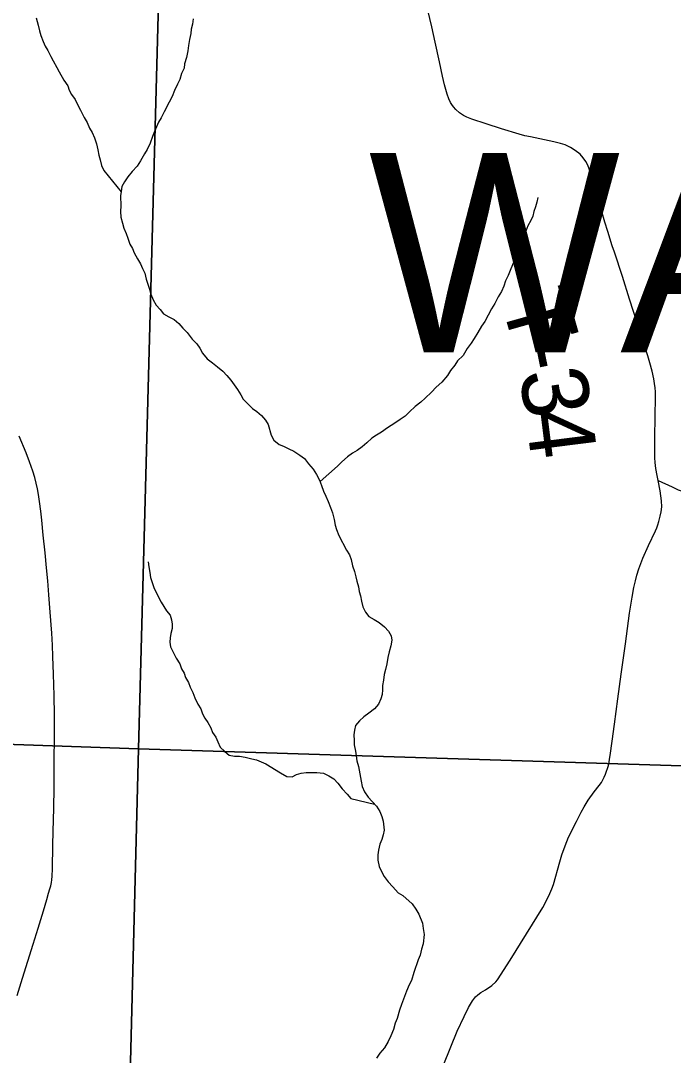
# Model space of a CAD drawing. Extents: x -7.9 to 76.1, y 0 to 22.
# Drawn here: x 6.095 to 6.653, y 14.979 to 15.864 of the extents above; entities that cross this region are included whole.
import ezdxf

# ---------------------------------------------------------------- set-up
doc = ezdxf.new("R2010")
doc.units = 0
for name, color, linetype in [('GM_X_Minor_River', 7, 'Continuous'), ('GM_X_Section', 7, 'Continuous'), ('GM_X_Township_Road', 7, 'Continuous'), ('GM_X_Township_Road_Text', 7, 'Continuous'), ('GM_X_Township_Text', 7, 'Continuous')]:
    doc.layers.add(name, color=color, linetype=linetype)

msp = doc.modelspace()

# ---------------------------------------------------------------- linework, layer by layer
at = {"layer": 'GM_X_Minor_River'}
for points in [[(6.10838, 15.86644), (6.10998, 15.86039), (6.11119, 15.85547), (6.11238, 15.85131), (6.11434, 15.84641), (6.11591, 15.84226), (6.11824, 15.83849), (6.12096, 15.8336), (6.12291, 15.82983), (6.12602, 15.82418), (6.12796, 15.82041), (6.13185, 15.81325), (6.13533, 15.80836), (6.13652, 15.80458), (6.13847, 15.80082), (6.14155, 15.79668), (6.1439, 15.79178), (6.14623, 15.78764), (6.14935, 15.78123), (6.15206, 15.77709), (6.15402, 15.77219), (6.15635, 15.76842), (6.1583, 15.7639), (6.15989, 15.7586), (6.1611, 15.75369), (6.16191, 15.74914), (6.16311, 15.74499), (6.16431, 15.74007), (6.16626, 15.73592), (6.1809, 15.71772)], [(6.24262, 15.86563), (6.24193, 15.86106), (6.24084, 15.85688), (6.24052, 15.85308), (6.23945, 15.84813), (6.23876, 15.8428), (6.23806, 15.83824), (6.237, 15.83253), (6.23518, 15.82719), (6.23485, 15.82339), (6.23264, 15.81881), (6.23119, 15.81385), (6.22935, 15.80966), (6.22677, 15.80431), (6.22456, 15.79934), (6.22197, 15.79437), (6.21791, 15.78597), (6.21533, 15.781), (6.2131, 15.77717), (6.21126, 15.77335), (6.20942, 15.76915), (6.20796, 15.76496), (6.20576, 15.75923), (6.20318, 15.75389), (6.20096, 15.75006), (6.19762, 15.74432), (6.19465, 15.73973), (6.19054, 15.73512), (6.18681, 15.73051), (6.18384, 15.7263), (6.18162, 15.72209), (6.18092, 15.71791), (6.18059, 15.71411), (6.1807, 15.70576), (6.18039, 15.70082), (6.18084, 15.69589), (6.18204, 15.69098), (6.18324, 15.68644), (6.1852, 15.68191), (6.18676, 15.67814), (6.18835, 15.67285), (6.19068, 15.66908), (6.19224, 15.66531), (6.19496, 15.66041), (6.19768, 15.6559), (6.19925, 15.65212), (6.2012, 15.64798), (6.2024, 15.64306), (6.20517, 15.63437), (6.20637, 15.63021), (6.20833, 15.6253), (6.21105, 15.62079), (6.21451, 15.61704), (6.21721, 15.61328)], [(6.53741, 15.71294), (6.53671, 15.70875), (6.53562, 15.70494), (6.53416, 15.70075), (6.53308, 15.69694), (6.53161, 15.69312), (6.52902, 15.68853), (6.52719, 15.68395), (6.52499, 15.67823), (6.52278, 15.67289), (6.52021, 15.66678), (6.518, 15.66219), (6.51655, 15.65724), (6.51435, 15.6519), (6.51215, 15.64617), (6.50994, 15.64159), (6.50848, 15.63701), (6.50627, 15.63243), (6.50368, 15.62784), (6.50072, 15.62211), (6.49775, 15.61751), (6.4922, 15.60681), (6.48923, 15.60259), (6.48627, 15.59724), (6.48292, 15.59226), (6.48033, 15.58805), (6.47698, 15.58345), (6.47364, 15.57771), (6.46877, 15.57309), (6.46655, 15.56927), (6.46282, 15.56466), (6.46022, 15.56045), (6.45537, 15.55469), (6.4505, 15.55045), (6.44638, 15.54622), (6.44114, 15.54122), (6.4374, 15.53775), (6.43252, 15.53389), (6.42765, 15.52927), (6.42391, 15.5258), (6.41978, 15.52271), (6.41527, 15.51961), (6.40888, 15.51573), (6.40362, 15.51186), (6.39948, 15.50953), (6.39535, 15.50681), (6.39123, 15.50296), (6.3871, 15.49949), (6.38298, 15.4964), (6.37884, 15.49406), (6.37471, 15.49097), (6.36984, 15.48673), (6.36609, 15.48288), (6.35114, 15.46966)], [(6.21721, 15.61328), (6.2218, 15.61069), (6.22638, 15.60847), (6.23022, 15.60511), (6.23369, 15.60098), (6.23753, 15.59724), (6.24177, 15.59161), (6.24562, 15.58749), (6.24833, 15.58373), (6.25066, 15.57958), (6.25452, 15.57471), (6.25911, 15.57135), (6.26333, 15.568), (6.26793, 15.56426), (6.27139, 15.56052), (6.27486, 15.55639), (6.27756, 15.55263), (6.28065, 15.5485), (6.28337, 15.54398), (6.28532, 15.54021), (6.29338, 15.53236), (6.29721, 15.52975), (6.30105, 15.52639), (6.30452, 15.52226), (6.30684, 15.5185), (6.30924, 15.50942), (6.31157, 15.50528), (6.31617, 15.50155), (6.31998, 15.50009), (6.32456, 15.49787), (6.32876, 15.49565), (6.33374, 15.4923), (6.33795, 15.48933), (6.34142, 15.48482), (6.34527, 15.48032), (6.34799, 15.4758), (6.35071, 15.47091), (6.35229, 15.46638), (6.35425, 15.46147), (6.3562, 15.45732), (6.35816, 15.4528), (6.36012, 15.44751), (6.3617, 15.44298), (6.3633, 15.43731), (6.36412, 15.43239), (6.36531, 15.42861), (6.36727, 15.4237), (6.37389, 15.41089), (6.37622, 15.40713), (6.37779, 15.40297), (6.379, 15.39768), (6.38058, 15.39276), (6.38178, 15.38823), (6.38259, 15.38444), (6.38417, 15.37953), (6.3846, 15.37574), (6.38579, 15.37197), (6.38661, 15.36742), (6.38781, 15.36251), (6.39015, 15.35799), (6.39286, 15.35423), (6.39744, 15.35163), (6.40165, 15.34904), (6.40625, 15.3453), (6.40971, 15.34156), (6.41204, 15.33779), (6.41247, 15.33401), (6.41177, 15.32906), (6.41032, 15.32411), (6.40925, 15.31916), (6.40819, 15.31383), (6.40712, 15.30889), (6.40604, 15.3047), (6.40534, 15.29976), (6.40465, 15.29519), (6.4047, 15.2914), (6.40437, 15.2876), (6.40328, 15.28379), (6.40107, 15.27921), (6.39771, 15.27537), (6.39283, 15.2715), (6.3887, 15.26841), (6.38496, 15.26495), (6.3816, 15.2611), (6.38052, 15.25692), (6.38019, 15.25312), (6.38026, 15.24818), (6.38031, 15.24439), (6.38152, 15.23909), (6.38195, 15.23493), (6.38277, 15.23076), (6.38397, 15.22585), (6.38641, 15.21336), (6.38723, 15.20882), (6.38919, 15.20429), (6.39228, 15.19978), (6.39959, 15.19191), (6.40231, 15.18739), (6.40388, 15.18324), (6.40508, 15.17908), (6.40593, 15.17151)], [(6.20415, 15.40097), (6.20459, 15.3968), (6.20541, 15.39188), (6.20623, 15.38772), (6.209, 15.37903), (6.21095, 15.37488), (6.21523, 15.36659), (6.21988, 15.35907), (6.22297, 15.35531), (6.22416, 15.35154), (6.22459, 15.34775), (6.22464, 15.34395), (6.22356, 15.33976), (6.22285, 15.33596), (6.22252, 15.33216), (6.22333, 15.32838), (6.22606, 15.32272), (6.22801, 15.31858), (6.23111, 15.31368), (6.23269, 15.30953), (6.23501, 15.30577), (6.2362, 15.30199), (6.23853, 15.29785), (6.2401, 15.29369), (6.24244, 15.28918), (6.24402, 15.28464), (6.24674, 15.27937), (6.24907, 15.27523), (6.25065, 15.27107), (6.25259, 15.2673), (6.2553, 15.26355), (6.25763, 15.25903), (6.25921, 15.25487), (6.26191, 15.25112), (6.26386, 15.24697), (6.26582, 15.24244), (6.26966, 15.2387), (6.27349, 15.23572), (6.27806, 15.23464), (6.28223, 15.2347), (6.28717, 15.23401), (6.29287, 15.23257), (6.29668, 15.23148), (6.30087, 15.23002), (6.30469, 15.22817), (6.31731, 15.22038), (6.32266, 15.21742), (6.32721, 15.2171), (6.33098, 15.21905), (6.33513, 15.22024), (6.3393, 15.22068), (6.34839, 15.22081), (6.35409, 15.22012), (6.35867, 15.21791), (6.36288, 15.21531), (6.36634, 15.21156), (6.3702, 15.20669), (6.37443, 15.20219), (6.37751, 15.19844), (6.39784, 15.19379)], [(6.40593, 15.17151), (6.40523, 15.16732), (6.40415, 15.16351), (6.40231, 15.15931), (6.40124, 15.15437), (6.40053, 15.15018), (6.40059, 15.14563), (6.4018, 15.14033), (6.40337, 15.13656), (6.40609, 15.13166), (6.40956, 15.12716), (6.41341, 15.12304), (6.41803, 15.11779), (6.42186, 15.11557), (6.42991, 15.10847), (6.43301, 15.10395), (6.43572, 15.09944), (6.43886, 15.09189), (6.4393, 15.08734), (6.44013, 15.08204), (6.43948, 15.07407), (6.43802, 15.06949), (6.43695, 15.06455), (6.43511, 15.06035), (6.43146, 15.04967), (6.42928, 15.04281), (6.42744, 15.03899), (6.42523, 15.03365), (6.42084, 15.02221), (6.41901, 15.01725), (6.4172, 15.01039), (6.41537, 15.00619), (6.41392, 15.00086), (6.41172, 14.99552), (6.40951, 14.99056), (6.40617, 14.9852), (6.40244, 14.98059), (6.39946, 14.97638)]]:
    msp.add_lwpolyline(points, dxfattribs=at)
at = {"layer": 'GM_X_Section'}
for points in [[(6.22272, 16.24155), (6.19582, 15.24098), (5.35319, 15.27029), (5.35544, 15.35372), (5.36783, 16.25786)], [(6.22272, 16.24155), (7.23119, 16.21858), (7.19836, 15.20958), (6.19582, 15.24098)], [(5.35319, 15.27029), (6.19582, 15.24098), (6.16992, 14.22528), (5.32336, 14.24371), (5.32522, 14.35061)], [(7.19836, 15.20958), (7.17682, 14.20532), (6.16992, 14.22528), (6.19582, 15.24098)]]:
    msp.add_lwpolyline(points, close=True, dxfattribs=at)
at = {"layer": 'GM_X_Township_Road'}
for points in [[(6.64046, 15.47066), (6.63955, 15.47501), (6.63845, 15.48089), (6.63785, 15.48617), (6.63758, 15.48998), (6.63749, 15.50715), (6.63784, 15.52549), (6.63815, 15.54185), (6.63807, 15.54645), (6.63782, 15.55007), (6.63741, 15.55369), (6.63675, 15.55754), (6.63518, 15.56417), (6.63339, 15.57123), (6.63161, 15.57718), (6.62751, 15.5897), (6.62262, 15.6046), (6.61586, 15.62593), (6.60977, 15.64515), (6.603, 15.66602), (6.6012, 15.67156), (6.59736, 15.68384), (6.59488, 15.69172), (6.59096, 15.70491), (6.587, 15.71908), (6.58324, 15.73247), (6.58122, 15.7383), (6.58002, 15.74101), (6.57859, 15.74359), (6.57634, 15.74679), (6.57362, 15.74991), (6.5695, 15.75316), (6.56533, 15.75569), (6.56078, 15.75774), (6.55687, 15.75908), (6.55103, 15.76057), (6.53121, 15.76462), (6.52636, 15.76569), (6.52143, 15.767), (6.50636, 15.77168), (6.4932, 15.77577), (6.48098, 15.77984), (6.47687, 15.78153), (6.47393, 15.7831), (6.47055, 15.78536), (6.46722, 15.78809), (6.46536, 15.79043), (6.4639, 15.79245), (6.46284, 15.79416), (6.46125, 15.79727), (6.45987, 15.80118), (6.45761, 15.80916), (6.45585, 15.81654), (6.45324, 15.82877), (6.44961, 15.8458), (6.44683, 15.85882), (6.4433, 15.87319)], [(6.09217, 15.03007), (6.09675, 15.04488), (6.10124, 15.05939), (6.10573, 15.07391), (6.10995, 15.08756), (6.11457, 15.10248), (6.11749, 15.11195), (6.11896, 15.11737), (6.12003, 15.12115), (6.12079, 15.12391), (6.12135, 15.12658), (6.12168, 15.12896), (6.12193, 15.132), (6.12217, 15.13833), (6.12269, 15.15847), (6.12299, 15.17018), (6.1233, 15.19028), (6.12357, 15.20767), (6.12382, 15.23303), (6.12398, 15.24906), (6.12407, 15.26994), (6.12374, 15.28675), (6.12317, 15.30478), (6.12269, 15.32004), (6.12225, 15.32975), (6.12168, 15.33997), (6.12036, 15.35797), (6.11928, 15.37277), (6.11839, 15.38485), (6.11724, 15.39579), (6.1159, 15.40884), (6.11437, 15.42382), (6.11307, 15.43676), (6.11223, 15.44429), (6.11116, 15.45276), (6.11033, 15.45851), (6.10935, 15.46353), (6.10836, 15.46821), (6.10705, 15.47314), (6.10541, 15.47857), (6.10255, 15.48661), (6.09961, 15.49437), (6.09381, 15.50857)], [(6.45697, 14.9712), (6.4685, 14.99928), (6.47449, 15.01189), (6.47819, 15.01954), (6.48172, 15.02537), (6.48419, 15.02866), (6.48616, 15.03055), (6.48871, 15.03236), (6.49257, 15.03474), (6.49824, 15.03861), (6.50145, 15.04165), (6.50301, 15.04337), (6.51375, 15.06023), (6.52774, 15.08276), (6.54165, 15.10518), (6.54485, 15.11111), (6.54773, 15.11711), (6.54954, 15.12114), (6.55085, 15.12492), (6.5562, 15.14418), (6.55809, 15.15024), (6.56072, 15.15796), (6.56384, 15.16528), (6.5705, 15.17884), (6.57445, 15.18682), (6.57708, 15.19142), (6.58053, 15.19709), (6.58563, 15.20424), (6.58998, 15.20967), (6.59184, 15.21212), (6.59311, 15.21446), (6.59427, 15.21685), (6.59532, 15.2193), (6.59626, 15.22179), (6.59708, 15.22432), (6.59779, 15.22689), (6.59838, 15.22949), (6.59885, 15.23211), (6.59943, 15.2354), (6.60116, 15.24756), (6.60312, 15.26205), (6.60604, 15.28374), (6.60889, 15.30478), (6.61247, 15.33073), (6.61596, 15.35702), (6.61816, 15.37079), (6.61967, 15.37899), (6.62097, 15.38484), (6.6222, 15.38951), (6.62392, 15.39504), (6.62736, 15.40407), (6.63201, 15.41493), (6.63806, 15.42747), (6.63929, 15.43012), (6.64026, 15.43272), (6.64108, 15.43543), (6.64226, 15.44), (6.6429, 15.44393), (6.64343, 15.44798), (6.64325, 15.45317), (6.64205, 15.46179), (6.64046, 15.47066)], [(6.64046, 15.47066), (6.65243, 15.46525), (6.65759, 15.46277), (6.66228, 15.46093), (6.66743, 15.45918), (6.6712, 15.45808), (6.68859, 15.4532), (6.70221, 15.44925), (6.71068, 15.44631), (6.72899, 15.43968), (6.73405, 15.43811), (6.74215, 15.4359), (6.75788, 15.43231), (6.77104, 15.42956), (6.783, 15.42744), (6.79009, 15.42633), (6.80021, 15.42504), (6.80846, 15.42421), (6.81646, 15.42353), (6.83559, 15.42263), (6.84481, 15.42182)]]:
    msp.add_lwpolyline(points, dxfattribs=at)

# ---------------------------------------------------------------- texts
at = {"layer": 'GM_X_Township_Road_Text'}
for s, rotation, p in [('T', 285.89713, (6.50543, 15.62504)), ('-', 281.44925, (6.51679, 15.5853)), ('3', 278.96141, (6.52131, 15.56307)), ('4', 277.21603, (6.5267, 15.52895))]:
    msp.add_text(s, height=0.05682, rotation=rotation, dxfattribs=at).set_placement(p)
at = {"layer": 'GM_X_Township_Text'}
msp.add_text('WAYNE', height=0.170455, rotation=0.00001, dxfattribs=at).set_placement((6.39276, 15.58035))

doc.saveas('drawing.dxf')
